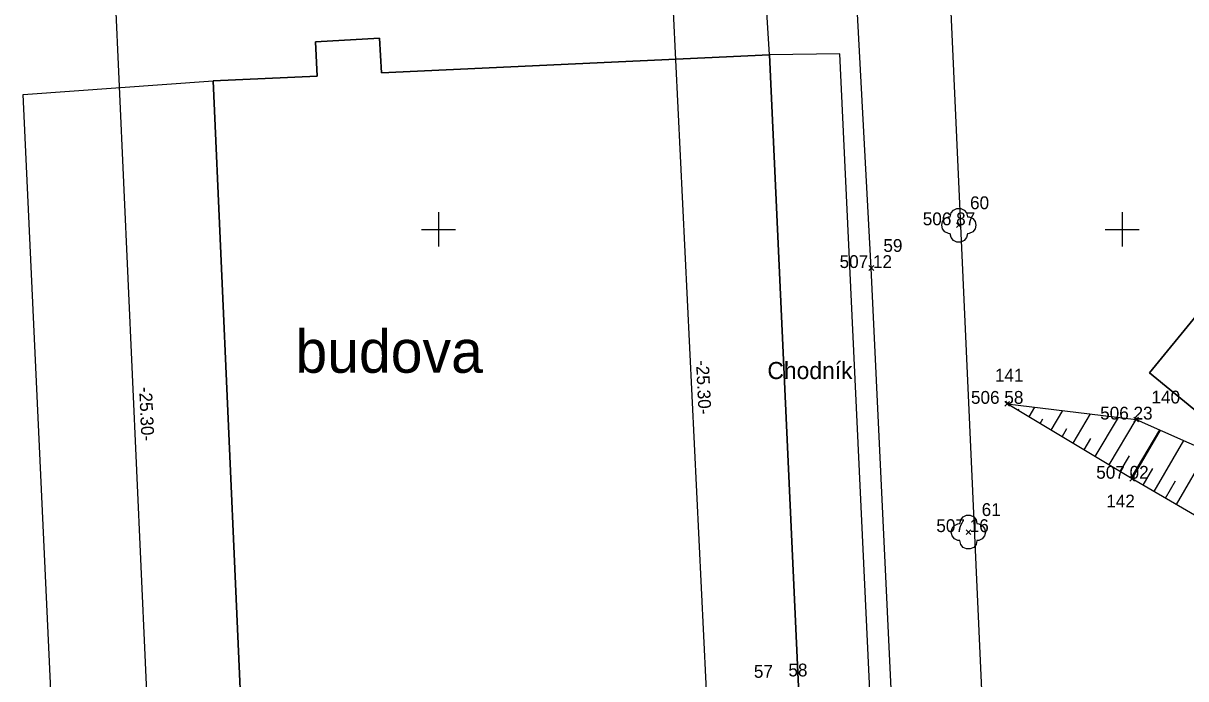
# Model space of a CAD drawing. Extents: x -408550 to -407654, y -1233019 to -1231230.
# Drawn here: x -407992.15 to -407958.14, y -1232033.14 to -1232013.97 of the extents above; entities that cross this region are included whole.
import ezdxf

# ---------------------------------------------------------------- set-up
doc = ezdxf.new("R2010")
doc.units = 0
for name, color, linetype in [('Level 1', 7, 'Continuous'), ('Level 11', 7, 'Continuous'), ('Level 13', 7, 'Continuous'), ('Level 16', 7, 'Continuous'), ('Level 23', 7, 'Continuous'), ('Level 26', 7, 'Continuous'), ('Level 27', 7, 'Continuous'), ('Level 28', 7, 'Continuous'), ('Level 40', 7, 'Continuous'), ('Level 5', 7, 'Continuous')]:
    doc.layers.add(name, color=color, linetype=linetype)

msp = doc.modelspace()

# ---------------------------------------------------------------- linework, layer by layer
at = {"layer": 'Level 1'}
for p, q in [((-407980, -1232019.5), (-407980, -1232020.5)), ((-407960, -1232019.5), (-407960, -1232020.5)), ((-407980.5, -1232020), (-407979.5, -1232020)), ((-407960.5, -1232020), (-407959.5, -1232020))]:
    msp.add_line(p, q, dxfattribs=at)
for points in [[(-407945.9, -1232007.95), (-407918.05, -1232030.75), (-407931.35, -1232047), (-407959.2, -1232024.19)], [(-407918.05, -1232030.75), (-407945.9, -1232007.95), (-407959.2, -1232024.19), (-407931.35, -1232047)], [(-407983.55, -1232015.52), (-407983.6, -1232014.52), (-407981.73, -1232014.41), (-407981.67, -1232015.42), (-407970.32, -1232014.9), (-407969.16, -1232040.17), (-407975.2, -1232040.45), (-407974.95, -1232045.12), (-407973.55, -1232045.08), (-407973.31, -1232049.36), (-407974.72, -1232049.44), (-407974.48, -1232053.95), (-407972.3, -1232056.28), (-407968.04, -1232052.23), (-407946.92, -1232075.07), (-407959.14, -1232086.36), (-407980.2, -1232063.57), (-407977.4, -1232060.97), (-407981.18, -1232056.94), (-407981.8, -1232045.69), (-407982.07, -1232040.75), (-407985.47, -1232040.9), (-407986.59, -1232015.66)], [(-407983.6, -1232014.52), (-407983.55, -1232015.52), (-407986.59, -1232015.66), (-407985.47, -1232040.9), (-407982.07, -1232040.75), (-407981.8, -1232045.69), (-407981.18, -1232056.94), (-407977.4, -1232060.97), (-407980.2, -1232063.57), (-407959.14, -1232086.36), (-407946.92, -1232075.07), (-407968.04, -1232052.23), (-407972.3, -1232056.28), (-407974.48, -1232053.95), (-407974.72, -1232049.44), (-407973.31, -1232049.36), (-407973.55, -1232045.08), (-407974.95, -1232045.12), (-407975.2, -1232040.45), (-407969.16, -1232040.17), (-407970.32, -1232014.9), (-407981.67, -1232015.42), (-407981.73, -1232014.41)]]:
    msp.add_lwpolyline(points, close=True, dxfattribs=at)
at = {"layer": 'Level 11'}
msp.add_lwpolyline([(-407989.46, -1232013.01), (-407973.21, -1232012.23), (-407971.98, -1232037.5), (-407977.95, -1232037.78), (-407977.733, -1232042.415), (-407976.39, -1232042.37), (-407976.14, -1232046.74), (-407977.45, -1232046.87), (-407977.009, -1232051.318), (-407974.962, -1232053.765), (-407970.82, -1232049.62), (-407949.71, -1232072.37), (-407961.89, -1232083.71), (-407983.01, -1232060.92), (-407980.3, -1232058.38), (-407984.06, -1232054.32), (-407985.01, -1232038.14), (-407988.32, -1232038.28)], close=True, dxfattribs=at)
at = {"layer": 'Level 13'}
for p, q in [((-407963.37, -1232025.1), (-407963.37, -1232025.1)), ((-407963.048, -1232025.293), (-407963.02, -1232025.245)), ((-407962.726, -1232025.485), (-407962.555, -1232025.199)), ((-407962.405, -1232025.678), (-407962.319, -1232025.535)), ((-407962.083, -1232025.87), (-407961.741, -1232025.298)), ((-407961.439, -1232026.255), (-407960.926, -1232025.397)), ((-407960.796, -1232026.64), (-407960.111, -1232025.497)), ((-407960.384, -1232026.887), (-407959.59, -1232025.56)), ((-407961.761, -1232026.063), (-407961.619, -1232025.825)), ((-407959.74, -1232027.272), (-407958.899, -1232025.865)), ((-407959.71, -1232027.29), (-407958.885, -1232025.871)), ((-407961.117, -1232026.448), (-407960.918, -1232026.115)), ((-407959.062, -1232027.667), (-407958.194, -1232026.176)), ((-407958.413, -1232028.044), (-407957.504, -1232026.481)), ((-407960.062, -1232027.079), (-407959.79, -1232026.624)), ((-407959.386, -1232027.479), (-407959.104, -1232026.994)), ((-407958.738, -1232027.856), (-407958.442, -1232027.347))]:
    msp.add_line(p, q, dxfattribs=at)
msp.add_lwpolyline([(-407928.84, -1232043.94), (-407924.2, -1232040.27), (-407930.21, -1232048.56), (-407926.93, -1232054.36), (-407924.42, -1232060.05), (-407929, -1232067.84), (-407940.94, -1232074.95), (-407931.23, -1232065.48), (-407926.71, -1232059.66), (-407931.56, -1232056.03), (-407936.78, -1232051.12), (-407946.91, -1232042.39), (-407951.89, -1232037.1), (-407955.66, -1232033.43), (-407956.53, -1232029.14), (-407959.71, -1232027.29), (-407963.37, -1232025.1), (-407959.59, -1232025.56), (-407955.74, -1232027.26), (-407941.12, -1232039.53), (-407932.66, -1232049.18), (-407931.8, -1232047.55)], close=True, dxfattribs=at)
at = {"layer": 'Level 16'}
msp.add_lwpolyline([(-407975.55, -1232046.38), (-407966.48, -1232045.77), (-407966.78, -1232037.84), (-407966.87, -1232034.48), (-407966.71, -1232034.46), (-407967.34, -1232021.13), (-407968.99, -1231990.5), (-407969.06, -1231986.9)], dxfattribs=at)
at = {"layer": 'Level 23'}
for points in [[(-407964.711, -1232019.949), (-407964.849, -1232019.811)], [(-407964.849, -1232019.949), (-407964.711, -1232019.811)], [(-407967.271, -1232021.199), (-407967.409, -1232021.061)], [(-407967.409, -1232021.199), (-407967.271, -1232021.061)], [(-407963.301, -1232025.169), (-407963.439, -1232025.031)], [(-407963.439, -1232025.169), (-407963.301, -1232025.031)], [(-407959.521, -1232025.629), (-407959.659, -1232025.491)], [(-407959.659, -1232025.629), (-407959.521, -1232025.491)], [(-407959.641, -1232027.359), (-407959.779, -1232027.221)], [(-407959.779, -1232027.359), (-407959.641, -1232027.221)], [(-407964.431, -1232028.919), (-407964.569, -1232028.781)], [(-407964.569, -1232028.919), (-407964.431, -1232028.781)]]:
    msp.add_lwpolyline(points, dxfattribs=at)
at = {"layer": 'Level 28'}
for points in [[(-407964.28, -1232019.88), (-407964.305, -1232019.988), (-407964.374, -1232020.075), (-407964.474, -1232020.124), (-407964.53, -1232020.13), (-407964.555, -1232020.238), (-407964.624, -1232020.325), (-407964.724, -1232020.374), (-407964.836, -1232020.374), (-407964.936, -1232020.325), (-407965.005, -1232020.238), (-407965.03, -1232020.13), (-407965.086, -1232020.124), (-407965.186, -1232020.075), (-407965.255, -1232019.988), (-407965.28, -1232019.88), (-407965.255, -1232019.771), (-407965.186, -1232019.684), (-407965.086, -1232019.636), (-407965.03, -1232019.63), (-407965.005, -1232019.521), (-407964.936, -1232019.434), (-407964.836, -1232019.386), (-407964.724, -1232019.386), (-407964.624, -1232019.434), (-407964.555, -1232019.521), (-407964.53, -1232019.63), (-407964.474, -1232019.636), (-407964.374, -1232019.684), (-407964.305, -1232019.771)], [(-407964, -1232028.85), (-407964.025, -1232028.959), (-407964.094, -1232029.046), (-407964.194, -1232029.094), (-407964.25, -1232029.1), (-407964.275, -1232029.209), (-407964.344, -1232029.296), (-407964.444, -1232029.344), (-407964.556, -1232029.344), (-407964.656, -1232029.296), (-407964.725, -1232029.209), (-407964.75, -1232029.1), (-407964.806, -1232029.094), (-407964.906, -1232029.046), (-407964.975, -1232028.959), (-407965, -1232028.85), (-407964.975, -1232028.742), (-407964.906, -1232028.655), (-407964.806, -1232028.606), (-407964.75, -1232028.6), (-407964.725, -1232028.492), (-407964.656, -1232028.405), (-407964.556, -1232028.356), (-407964.444, -1232028.356), (-407964.344, -1232028.405), (-407964.275, -1232028.492), (-407964.25, -1232028.6), (-407964.194, -1232028.606), (-407964.094, -1232028.655), (-407964.025, -1232028.742)]]:
    msp.add_lwpolyline(points, close=True, dxfattribs=at)
for points in [[(-407964.793, -1232019.88), (-407964.78, -1232019.88), (-407964.768, -1232019.88)], [(-407964.512, -1232028.85), (-407964.5, -1232028.85), (-407964.488, -1232028.85)]]:
    msp.add_lwpolyline(points, dxfattribs=at)
at = {"layer": 'Level 5'}
for p, q in [((-407966.08, -1231990.2), (-407963.9, -1232038.18)), ((-407967.15, -1232038.39), (-407968.26, -1232014.87)), ((-407992.15, -1232016.06), (-407986.59, -1232015.66)), ((-407990.98, -1232041.41), (-407992.15, -1232016.06))]:
    msp.add_line(p, q, dxfattribs=at)
msp.add_lwpolyline([(-407968.26, -1232014.87), (-407970.32, -1232014.9), (-407972.16, -1231985.32), (-407972.21, -1231984.54)], dxfattribs=at)

# ---------------------------------------------------------------- texts
at = {"layer": 'Level 1'}
for rotation, p in [(272.7958, (-407972.47, -1232023.832)), (272.5666, (-407988.761, -1232024.612))]:
    msp.add_text('-25.30-', height=0.375, rotation=rotation, dxfattribs=at).set_placement(p)
at = {"layer": 'Level 26'}
for s, p in [('60', (-407964.452, -1232019.41)), ('59', (-407966.987, -1232020.66)), ('141', (-407963.725, -1232024.45)), ('140', (-407959.143, -1232025.09)), ('142', (-407960.467, -1232028.131)), ('61', (-407964.112, -1232028.38)), ('58', (-407969.766, -1232033.07)), ('57', (-407970.776, -1232033.11))]:
    msp.add_text(s, height=0.375, dxfattribs=at).set_placement(p)
at = {"layer": 'Level 27'}
msp.add_text('budova', height=1.25, dxfattribs=at).set_placement((-407984.188, -1232024.192))
at = {"layer": 'Level 28'}
msp.add_text('Chodník', height=0.5, dxfattribs=at).set_placement((-407970.38, -1232024.377))
at = {"layer": 'Level 40'}
for s, p in [('506 87', (-407965.835, -1232019.88)), ('507 12', (-407968.268, -1232021.13)), ('506 58', (-407964.425, -1232025.1)), ('506 23', (-407960.645, -1232025.56)), ('507 02', (-407960.76, -1232027.29)), ('507 16', (-407965.438, -1232028.85))]:
    msp.add_text(s, height=0.375, dxfattribs=at).set_placement(p)

doc.saveas('drawing.dxf')
